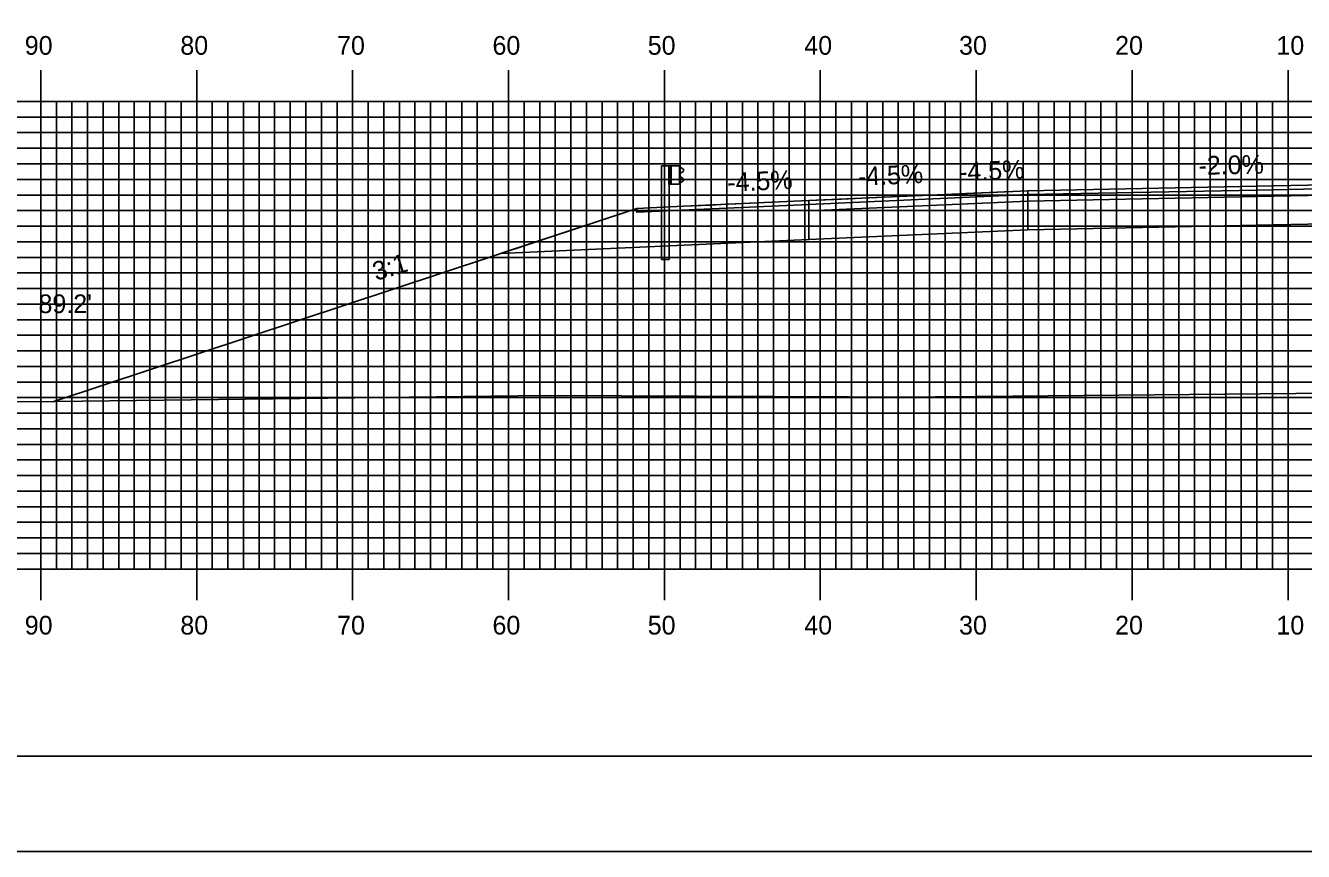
# Model space of a CAD drawing. Extents: x 1757069 to 1757412, y 442591 to 442811.
# Drawn here: x 1757143.6 to 1757225.6, y 442590.5 to 442643.5 of the extents above; entities that cross this region are included whole.
import ezdxf

# ---------------------------------------------------------------- set-up
doc = ezdxf.new("R2010")
doc.units = 0
for name, color, linetype in [('ANNOTATION', 7, 'Continuous'), ('BORDER', 7, 'Continuous'), ('D_Guardrail_Beam_Lt', 7, 'Continuous'), ('D_Roadway_Centerline', 7, 'Continuous'), ('D_Roadway_Edge_Shoulder', 7, 'Continuous'), ('D_Roadway_Edge_TW', 7, 'Continuous'), ('D_Roadway_FinishedGrade', 7, 'Continuous'), ('D_Roadway_Pavement', 7, 'Continuous'), ('D_Roadway_SlopeLines', 7, 'Continuous'), ('D_Roadway_SubGrade', 7, 'Continuous'), ('D_Text_Standard', 7, 'Continuous'), ('H_V ANNOTATION', 7, 'Continuous'), ('MAJOR', 7, 'Continuous'), ('MINOR', 7, 'Continuous'), ('PLOT BOUNDARY', 7, 'Continuous'), ('S_Roadway_Centerline', 7, 'Continuous')]:
    doc.layers.add(name, color=color, linetype=linetype)

msp = doc.modelspace()

# ---------------------------------------------------------------- linework, layer by layer
at = {"layer": 'BORDER'}
msp.add_lwpolyline([(1757084.996, 442596.665), (1757404.996, 442596.665), (1757404.996, 442806.665), (1757084.996, 442806.665)], close=True, dxfattribs=at)
at = {"layer": 'D_Guardrail_Beam_Lt'}
for p, q in [((1757184.401, 442634.527), (1757184.401, 442628.527)), ((1757184.872, 442634.527), (1757184.401, 442634.527)), ((1757185.56, 442634.527), (1757184.872, 442634.527)), ((1757184.872, 442634.527), (1757184.872, 442633.36)), ((1757184.935, 442634.527), (1757184.935, 442633.36)), ((1757185.039, 442634.527), (1757185.039, 442633.36)), ((1757185.56, 442633.36), (1757185.56, 442634.527)), ((1757185.56, 442634.443), (1757185.634, 442634.429)), ((1757185.564, 442633.978), (1757185.564, 442633.908)), ((1757185.793, 442634.179), (1757185.598, 442634.043)), ((1757185.598, 442633.844), (1757185.793, 442633.708)), ((1757185.65, 442634.422), (1757185.793, 442634.322)), ((1757184.872, 442633.36), (1757185.56, 442633.36)), ((1757184.893, 442628.527), (1757184.893, 442633.36)), ((1757185.634, 442633.458), (1757185.56, 442633.443)), ((1757185.793, 442633.565), (1757185.65, 442633.465)), ((1757184.893, 442628.527), (1757184.401, 442628.527))]:
    msp.add_line(p, q, dxfattribs=at)
for centre, major_axis, start_param, end_param in [((1757185.643, 442633.978), (-0.0789, 0), 5.323254, 6.283185), ((1757185.643, 442633.908), (-0.0789, 0), 6.283185, 7.243116), ((1757185.626, 442634.388), (0.0417, 0), 0.959931, 1.376053), ((1757185.743, 442634.251), (0.0877, 0), 5.323254, 7.243116), ((1757185.626, 442633.499), (0.0417, 0), 4.907132, 5.323254), ((1757185.743, 442633.636), (0.0877, 0), 5.323254, 7.243116)]:
    msp.add_ellipse(centre, major_axis=major_axis, ratio=0.995501, start_param=start_param, end_param=end_param, dxfattribs=at)
at = {"layer": 'D_Roadway_Centerline'}
msp.add_lwpolyline([(1757145.436, 442619.422), (1757182.819, 442631.808), (1757185.83, 442631.943), (1757187.529, 442632.02), (1757188.24, 442632.052), (1757193.861, 442632.305), (1757195.466, 442632.378), (1757196.397, 442632.42), (1757197.694, 442632.478), (1757201.152, 442632.634), (1757202.266, 442632.684), (1757203.924, 442632.759), (1757207.914, 442632.939), (1757222.596, 442633.233), (1757234.596, 442633.473), (1757246.596, 442633.233), (1757254.596, 442632.913), (1757262.622, 442630.906)], dxfattribs=at)
at = {"layer": 'D_Roadway_Edge_Shoulder'}
msp.add_lwpolyline([(1757193.861, 442632.305), (1757185.83, 442631.943), (1757185.83, 442631.943), (1757182.819, 442631.808), (1757182.819, 442631.558), (1757193.861, 442632.055)], close=True, dxfattribs=at)
at = {"layer": 'D_Roadway_Edge_TW'}
for points in [[(1757222.596, 442633.233), (1757207.914, 442632.939), (1757207.914, 442632.689), (1757222.596, 442632.983)], [(1757222.596, 442632.983), (1757222.596, 442633.233), (1757234.596, 442633.473), (1757246.596, 442633.233), (1757246.596, 442632.983), (1757234.596, 442633.223)], [(1757207.914, 442632.939), (1757193.861, 442632.305), (1757193.861, 442632.055), (1757207.914, 442632.689)]]:
    msp.add_lwpolyline(points, close=True, dxfattribs=at)
msp.add_lwpolyline([(1757207.914, 442632.939), (1757207.914, 442632.689)], dxfattribs=at)
at = {"layer": 'D_Roadway_FinishedGrade'}
msp.add_line((1757193.861, 442629.805), (1757174.085, 442628.914), dxfattribs=at)
at = {"layer": 'D_Roadway_Pavement'}
for points in [[(1757222.596, 442632.983), (1757207.914, 442632.689), (1757207.914, 442632.272), (1757222.596, 442632.566)], [(1757222.596, 442632.566), (1757222.596, 442632.983), (1757234.596, 442633.223), (1757246.596, 442632.983), (1757246.596, 442632.566), (1757234.596, 442632.806)], [(1757207.914, 442632.689), (1757193.861, 442632.055), (1757193.861, 442631.639), (1757207.914, 442632.272)]]:
    msp.add_lwpolyline(points, close=True, dxfattribs=at)
for points in [[(1757207.914, 442632.689), (1757207.914, 442632.272)], [(1757207.914, 442632.689), (1757207.914, 442632.272)], [(1757193.861, 442632.055), (1757193.861, 442631.639)], [(1757193.861, 442632.055), (1757193.861, 442631.639)]]:
    msp.add_lwpolyline(points, dxfattribs=at)
at = {"layer": 'D_Roadway_SlopeLines'}
msp.add_lwpolyline([(1757182.819, 442631.808), (1757145.436, 442619.422)], dxfattribs=at)
at = {"layer": 'D_Roadway_SubGrade'}
for points in [[(1757207.914, 442632.272), (1757193.861, 442631.639), (1757193.861, 442629.805), (1757207.914, 442630.439)], [(1757222.596, 442632.566), (1757207.914, 442632.272), (1757207.914, 442630.439), (1757222.596, 442630.733)], [(1757222.596, 442630.733), (1757222.596, 442632.566), (1757234.596, 442632.806), (1757246.596, 442632.566), (1757246.596, 442630.733), (1757234.596, 442630.973)], [(1757193.861, 442631.639), (1757193.861, 442632.055), (1757182.819, 442631.558), (1757182.819, 442631.808), (1757174.085, 442628.914), (1757193.861, 442629.805)]]:
    msp.add_lwpolyline(points, close=True, dxfattribs=at)
msp.add_lwpolyline([(1757207.914, 442632.272), (1757207.914, 442630.439)], dxfattribs=at)
at = {"layer": 'MAJOR'}
for p, q in [((1757144.596, 442640.669), (1757144.596, 442638.665)), ((1757154.596, 442640.669), (1757154.596, 442638.665)), ((1757164.596, 442640.669), (1757164.596, 442638.665)), ((1757174.596, 442640.669), (1757174.596, 442638.665)), ((1757184.596, 442640.669), (1757184.596, 442638.665)), ((1757194.596, 442640.669), (1757194.596, 442638.665)), ((1757204.596, 442640.669), (1757204.596, 442638.665)), ((1757214.596, 442640.669), (1757214.596, 442638.665)), ((1757224.596, 442640.669), (1757224.596, 442638.665)), ((1757094.596, 442638.665), (1757374.596, 442638.665)), ((1757094.596, 442638.665), (1757374.596, 442638.665)), ((1757144.596, 442608.665), (1757144.596, 442638.665)), ((1757154.596, 442608.665), (1757154.596, 442638.665)), ((1757164.596, 442608.665), (1757164.596, 442638.665)), ((1757174.596, 442608.665), (1757174.596, 442638.665)), ((1757184.596, 442608.665), (1757184.596, 442638.665)), ((1757194.596, 442608.665), (1757194.596, 442638.665)), ((1757204.596, 442608.665), (1757204.596, 442638.665)), ((1757214.596, 442608.665), (1757214.596, 442638.665)), ((1757224.596, 442608.665), (1757224.596, 442638.665)), ((1757094.596, 442633.665), (1757374.596, 442633.665)), ((1757094.596, 442628.665), (1757374.596, 442628.665)), ((1757094.596, 442623.665), (1757374.596, 442623.665)), ((1757094.596, 442618.665), (1757374.596, 442618.665)), ((1757094.596, 442613.665), (1757374.596, 442613.665)), ((1757094.596, 442608.665), (1757374.596, 442608.665)), ((1757094.596, 442608.665), (1757374.596, 442608.665)), ((1757144.596, 442606.661), (1757144.596, 442608.665)), ((1757154.596, 442606.661), (1757154.596, 442608.665)), ((1757164.596, 442606.661), (1757164.596, 442608.665)), ((1757174.596, 442606.661), (1757174.596, 442608.665)), ((1757184.596, 442606.661), (1757184.596, 442608.665)), ((1757194.596, 442606.661), (1757194.596, 442608.665)), ((1757204.596, 442606.661), (1757204.596, 442608.665)), ((1757214.596, 442606.661), (1757214.596, 442608.665)), ((1757224.596, 442606.661), (1757224.596, 442608.665))]:
    msp.add_line(p, q, dxfattribs=at)
at = {"layer": 'MINOR'}
for p, q in [((1757145.596, 442608.665), (1757145.596, 442638.665)), ((1757146.596, 442608.665), (1757146.596, 442638.665)), ((1757147.596, 442608.665), (1757147.596, 442638.665)), ((1757148.596, 442608.665), (1757148.596, 442638.665)), ((1757149.596, 442608.665), (1757149.596, 442638.665)), ((1757150.596, 442608.665), (1757150.596, 442638.665)), ((1757151.596, 442608.665), (1757151.596, 442638.665)), ((1757152.596, 442608.665), (1757152.596, 442638.665)), ((1757153.596, 442608.665), (1757153.596, 442638.665)), ((1757155.596, 442608.665), (1757155.596, 442638.665)), ((1757156.596, 442608.665), (1757156.596, 442638.665)), ((1757157.596, 442608.665), (1757157.596, 442638.665)), ((1757158.596, 442608.665), (1757158.596, 442638.665)), ((1757159.596, 442608.665), (1757159.596, 442638.665)), ((1757160.596, 442608.665), (1757160.596, 442638.665)), ((1757161.596, 442608.665), (1757161.596, 442638.665)), ((1757162.596, 442608.665), (1757162.596, 442638.665)), ((1757163.596, 442608.665), (1757163.596, 442638.665)), ((1757165.596, 442608.665), (1757165.596, 442638.665)), ((1757166.596, 442608.665), (1757166.596, 442638.665)), ((1757167.596, 442608.665), (1757167.596, 442638.665)), ((1757168.596, 442608.665), (1757168.596, 442638.665)), ((1757169.596, 442608.665), (1757169.596, 442638.665)), ((1757170.596, 442608.665), (1757170.596, 442638.665)), ((1757171.596, 442608.665), (1757171.596, 442638.665)), ((1757172.596, 442608.665), (1757172.596, 442638.665)), ((1757173.596, 442608.665), (1757173.596, 442638.665)), ((1757175.596, 442608.665), (1757175.596, 442638.665)), ((1757176.596, 442608.665), (1757176.596, 442638.665)), ((1757177.596, 442608.665), (1757177.596, 442638.665)), ((1757178.596, 442608.665), (1757178.596, 442638.665)), ((1757179.596, 442608.665), (1757179.596, 442638.665)), ((1757180.596, 442608.665), (1757180.596, 442638.665)), ((1757181.596, 442608.665), (1757181.596, 442638.665)), ((1757182.596, 442608.665), (1757182.596, 442638.665)), ((1757183.596, 442608.665), (1757183.596, 442638.665)), ((1757185.596, 442608.665), (1757185.596, 442638.665)), ((1757186.596, 442608.665), (1757186.596, 442638.665)), ((1757187.596, 442608.665), (1757187.596, 442638.665)), ((1757188.596, 442608.665), (1757188.596, 442638.665)), ((1757189.596, 442608.665), (1757189.596, 442638.665)), ((1757190.596, 442608.665), (1757190.596, 442638.665)), ((1757191.596, 442608.665), (1757191.596, 442638.665)), ((1757192.596, 442608.665), (1757192.596, 442638.665)), ((1757193.596, 442608.665), (1757193.596, 442638.665)), ((1757195.596, 442608.665), (1757195.596, 442638.665)), ((1757196.596, 442608.665), (1757196.596, 442638.665)), ((1757197.596, 442608.665), (1757197.596, 442638.665)), ((1757198.596, 442608.665), (1757198.596, 442638.665)), ((1757199.596, 442608.665), (1757199.596, 442638.665)), ((1757200.596, 442608.665), (1757200.596, 442638.665)), ((1757201.596, 442608.665), (1757201.596, 442638.665)), ((1757202.596, 442608.665), (1757202.596, 442638.665)), ((1757203.596, 442608.665), (1757203.596, 442638.665)), ((1757205.596, 442608.665), (1757205.596, 442638.665)), ((1757206.596, 442608.665), (1757206.596, 442638.665)), ((1757207.596, 442608.665), (1757207.596, 442638.665)), ((1757208.596, 442608.665), (1757208.596, 442638.665)), ((1757209.596, 442608.665), (1757209.596, 442638.665)), ((1757210.596, 442608.665), (1757210.596, 442638.665)), ((1757211.596, 442608.665), (1757211.596, 442638.665)), ((1757212.596, 442608.665), (1757212.596, 442638.665)), ((1757213.596, 442608.665), (1757213.596, 442638.665)), ((1757215.596, 442608.665), (1757215.596, 442638.665)), ((1757216.596, 442608.665), (1757216.596, 442638.665)), ((1757217.596, 442608.665), (1757217.596, 442638.665)), ((1757218.596, 442608.665), (1757218.596, 442638.665)), ((1757219.596, 442608.665), (1757219.596, 442638.665)), ((1757220.596, 442608.665), (1757220.596, 442638.665)), ((1757221.596, 442608.665), (1757221.596, 442638.665)), ((1757222.596, 442608.665), (1757222.596, 442638.665)), ((1757223.596, 442608.665), (1757223.596, 442638.665)), ((1757094.596, 442637.665), (1757374.596, 442637.665)), ((1757094.596, 442636.665), (1757374.596, 442636.665)), ((1757094.596, 442635.665), (1757374.596, 442635.665)), ((1757094.596, 442634.665), (1757374.596, 442634.665)), ((1757094.596, 442632.665), (1757374.596, 442632.665)), ((1757094.596, 442631.665), (1757374.596, 442631.665)), ((1757094.596, 442630.665), (1757374.596, 442630.665)), ((1757094.596, 442629.665), (1757374.596, 442629.665)), ((1757094.596, 442627.665), (1757374.596, 442627.665)), ((1757094.596, 442626.665), (1757374.596, 442626.665)), ((1757094.596, 442625.665), (1757374.596, 442625.665)), ((1757094.596, 442624.665), (1757374.596, 442624.665)), ((1757094.596, 442622.665), (1757374.596, 442622.665)), ((1757094.596, 442621.665), (1757374.596, 442621.665)), ((1757094.596, 442620.665), (1757374.596, 442620.665)), ((1757094.596, 442619.665), (1757374.596, 442619.665)), ((1757094.596, 442617.665), (1757374.596, 442617.665)), ((1757094.596, 442616.665), (1757374.596, 442616.665)), ((1757094.596, 442615.665), (1757374.596, 442615.665)), ((1757094.596, 442614.665), (1757374.596, 442614.665)), ((1757094.596, 442612.665), (1757374.596, 442612.665)), ((1757094.596, 442611.665), (1757374.596, 442611.665)), ((1757094.596, 442610.665), (1757374.596, 442610.665)), ((1757094.596, 442609.665), (1757374.596, 442609.665))]:
    msp.add_line(p, q, dxfattribs=at)
at = {"layer": 'PLOT BOUNDARY'}
msp.add_lwpolyline([(1757068.809, 442590.547), (1757408.809, 442590.547), (1757408.809, 442810.547), (1757068.809, 442810.547)], close=True, dxfattribs=at)
at = {"layer": 'S_Roadway_Centerline'}
msp.add_lwpolyline([(1757094.596, 442619.178), (1757096.346, 442619.187), (1757115.032, 442619.281), (1757138.197, 442619.386), (1757141.934, 442619.403), (1757145.494, 442619.421), (1757176.97, 442619.809), (1757201.316, 442619.703), (1757201.961, 442619.712), (1757202.394, 442619.711), (1757227.351, 442619.942), (1757258.335, 442619.747), (1757260.686, 442619.723), (1757265.627, 442619.7), (1757288.044, 442619.123), (1757304.622, 442618.867), (1757310.38, 442618.842), (1757330.151, 442618.649), (1757342.337, 442618.731), (1757360.532, 442618.925), (1757374.596, 442618.782)], dxfattribs=at)

# ---------------------------------------------------------------- texts
at = {"layer": 'ANNOTATION'}
for s, rotation, p in [('-4.5%', 2.58136, (1757197.024, 442633.25)), ('-4.5%', 2.58161, (1757203.52, 442633.543)), ('-2.0%', 1.14576, (1757218.861, 442633.958)), ('-4.5%', 2.58114, (1757188.651, 442632.873)), ('3:1', 16.82899, (1757166.095, 442627.147))]:
    msp.add_text(s, height=1.2, rotation=rotation, dxfattribs=at).set_placement(p)
at = {"layer": 'D_Text_Standard'}
msp.add_text("89.2'", height=1.2, dxfattribs=at).set_placement((1757144.449, 442625.086))
at = {"layer": 'H_V ANNOTATION'}
for s, p in [('90', (1757143.568, 442641.665)), ('80', (1757153.547, 442641.665)), ('70', (1757163.6, 442641.665)), ('60', (1757173.568, 442641.665)), ('50', (1757183.525, 442641.665)), ('40', (1757193.568, 442641.665)), ('30', (1757203.493, 442641.665)), ('20', (1757213.504, 442641.665)), ('10', (1757223.847, 442641.665)), ('90', (1757143.568, 442604.465)), ('80', (1757153.547, 442604.465)), ('70', (1757163.6, 442604.465)), ('60', (1757173.568, 442604.465)), ('50', (1757183.525, 442604.465)), ('40', (1757193.568, 442604.465)), ('30', (1757203.493, 442604.465)), ('20', (1757213.504, 442604.465)), ('10', (1757223.847, 442604.465))]:
    msp.add_text(s, height=1.2, dxfattribs=at).set_placement(p)

doc.saveas('drawing.dxf')
